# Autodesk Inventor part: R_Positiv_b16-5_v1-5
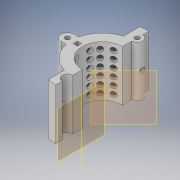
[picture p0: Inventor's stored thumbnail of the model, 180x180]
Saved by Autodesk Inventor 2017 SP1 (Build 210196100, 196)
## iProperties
Part Number: R_Positiv_b16-5_v1-5
Material: Generisch
Document SubType Name: Modeling
Designer: haesner
Density: 1 g/cm^3
Appearance: Vorgabe
Part Number: R_Positiv_b16-5_v1-5_3D-Druck
Author: haesner
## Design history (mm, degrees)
sketch "Skizze1"
  geometry: L1 (-26.9, 0)-(7.4, 0) reference; L2 (0, 22)-(0, 19); L3 (0, 9.5)-(0, 14); L4 (0, -22)-(0, -19); L5 (0, -9.5)-(0, -14); L6 (0, -30.8)-(0, 30.8) reference; C1 r 1.15 at (-16.5, 0); C2 r 1.15 at (0, 16.5); A1 r 22 centre (0, 0) between (0, 22) and (0, -22); A2 r 9.5 centre (0, 0) between (0, 9.5) and (0, -9.5); A3 r 2.5 centre (0, 16.5) between (0, 14) and (0, 19); A4 r 2.5 centre (0, -16.5) between (0, -14) and (0, -19); 1 further point
  constraints: 8 end point, 8 point on circle, 6 centre point, 4 collinear, 3 coincident, 3 point on line, 3 vertical, 1 equal radius
  dimensions: "d1" = 22 radius of A1; "d2" = 9.5 radius of A2; "d5" = 2.3 diameter of C1 (= d8); "d7" = 16.5 distance from line of L1 A3.centre (= d12); "d8" = 2.3 diameter of C2; "d10" = 16.5 distance from line of L6 C1.centre (= d12); "d11" = 2.5 radius of A4; "d12" = 16.5 distance from line of L1 A4.centre
extrude "Extrusion2" new body sketch "Skizze1" distance "d13" = 3; taper "d14" = 0 deg
sketch "Skizze5"
  geometry: L1 (-4, -21.633)-(-4, -13.937); L2 (-4, 21.633)-(-4, 13.937); L3 (0, 19)-(0, 22) reference; L4 (0, 9.5)-(0, 14) reference; L5 (0, -22)-(0, -19) reference; L6 (0, -14)-(0, -9.5) reference; L7 (-26.9, 0)-(7.4, 0) reference; L8 (-16.5, -3)-(-14.186, -3); L9 (-16.5, 3)-(-14.186, 3); C1 r 1.15 at (0, 16.5) reference; C2 r 1.15 at (-16.5, 0) reference; A1 r 14.5 centre (0, 0) between (-4, 13.937) and (-4, -13.937); A2 r 9.5 centre (0, 0) between (0, 9.5) and (0, -9.5) reference; A3 r 22 centre (0, 0) between (0, 22) and (-4, 21.633); A4 r 22 centre (0, 0) between (-4, -21.633) and (0, -22); A5 r 2.5 centre (0, 16.5) between (0, 14) and (0, 19) reference; A6 r 2.5 centre (0, -16.5) between (0, -14) and (0, -19) reference; A7 r 3 centre (-16.5, 0) between (-16.5, 3) and (-16.5, -3)
  constraints: 10 point on circle, 8 end point, 4 centre point, 4 coincident, 2 horizontal, 2 vertical, 1 concentric, 1 other
  dimensions: "d22" = 14.5 radius of A1; "d100" = 4 distance between parallel lines of L3 L2; "d101" = 4 distance between parallel lines of L5 L1 (= d100); "d119" = 3 radius of A7; "d120" = 6 distance between parallel lines of L9 L8
extrude "Extrusion5" join sketch "Skizze5" distance "d27" = 18; taper "d28" = 0 deg
workplane "Arbeitsebene4"
sketch "Skizze10"
  geometry: L1 (0, 19)-(0, 22); L2 (0, 9.5)-(0, 14); L3 (0, -14)-(0, -9.5); L4 (0, -22)-(0, -19); C1 r 1.15 at (0, 16.5); C2 r 1.15 at (-16.5, 0) reference; A1 r 22 centre (0, 0) between (0, 22) and (0, -22); A2 r 2.5 centre (0, 16.5) between (0, 14) and (0, 19); A3 r 9.5 centre (0, 0) between (0, 9.5) and (0, -9.5); A4 r 2.5 centre (0, -16.5) between (0, -14) and (0, -19)
  constraints: 8 end point, 8 point on circle, 5 centre point
extrude "Extrusion9" join sketch "Skizze10" distance "d69" = 3; taper "d70" = 0 deg
sketch "Skizze6"
  geometry: L1 (14.4, 7.821)-(14.4, 3.321); L2 (14.4, 3.321)-(10.8, 3.321); L3 (10.8, 3.321)-(10.8, 7.821); L4 (10.8, 7.821)-(7.2, 7.821); L5 (7.2, 7.821)-(7.2, 3.321); L6 (7.2, 3.321)-(3.6, 3.321); L7 (3.6, 3.321)-(3.6, 7.821); L8 (3.6, 7.821)-(0, 7.821); L9 (0, 7.821)-(0, 3.321); L10 (22.585, 5.571)-(-0.758, 5.571); L11 (14.4, 7.821)-(18, 7.821); L12 (18, 7.821)-(18, 3.321); L13 (-8.117, 7.071)-(27.702, 7.071) reference; L14 (-3, 47.871)-(-3, -19.94) reference; 1 further point
  constraints: 24 end point, 7 perpendicular, 6 equal length, 5 point on line, 2 horizontal, 1 vertical, 1 other
  dimensions: "d31" = 3.6 distance of L1.end L2.end; "d32" = 4.5 distance of L1.start L1.end; "d114" = 3 distance between parallel lines of L9 L14; "d115" = 0.75 distance between parallel lines of L13 L11
hole "Bohrung1" sketch "Skizze6" at (14.4, 3.321), (14.4, 7.821), (10.8, 7.821), (10.8, 3.321), (7.2, 3.321), (7.2, 7.821), (3.6, 7.821), (0, 7.821), (0, 3.321), (3.6, 3.321), (18, 7.821), (18, 3.321) diameter "d34" = 2.5; stored, may be unused: countersink angle "d38" = 90 deg, drill point angle "d40" = 118 deg; dims "d35" = 6, "d36" = 4, "d37" = 2, "d39" = 4
workplane "Arbeitsebene5"
sketch "Skizze7"
  geometry: L1 (14.4, -7.821)-(14.4, -3.321); L2 (14.4, -3.321)-(10.8, -3.321); L3 (10.8, -3.321)-(10.8, -7.821); L4 (10.8, -7.821)-(7.2, -7.821); L5 (7.2, -7.821)-(7.2, -3.321); L6 (7.2, -3.321)-(3.6, -3.321); L7 (3.6, -3.321)-(3.6, -7.821); L8 (3.6, -7.821)-(0, -7.821); L9 (0, -7.821)-(0, -3.321); L10 (24.128, -5.571)-(-5.905, -5.571); L11 (-11.912, -7.071)-(30.135, -7.071) reference; L12 (-3, 19.94)-(-3, -47.871) reference; L13 (14.4, -7.821)-(18, -7.821); L14 (18, 0.243)-(18, -20.071) reference; L15 (18, -7.821)-(18, -3.321); 2 further points
  constraints: 24 end point, 8 perpendicular, 6 equal length, 5 point on line, 1 horizontal, 1 vertical, 1 other
  dimensions: "d41" = 4.5 distance of L1.start L1.end; "d42" = 3.6 distance of L1.end L2.end; "d116" = 3 distance between parallel lines of L12 L9; "d117" = 0.75 distance between parallel lines of L11 L13
hole "Bohrung2" sketch "Skizze7" at (14.4, -7.821), (14.4, -3.321), (10.8, -3.321), (10.8, -7.821), (7.2, -7.821), (7.2, -3.321), (3.6, -3.321), (3.6, -7.821), (0, -7.821), (0, -3.321), (18, -3.321), (18, -7.821) diameter "d44" = 2.5; stored, may be unused: countersink angle "d48" = 90 deg, drill point angle "d50" = 118 deg; dims "d45" = 6, "d46" = 4, "d47" = 2, "d49" = 4
workplane "Arbeitsebene6"
sketch "Skizze8"
  geometry: L1 (-14.4, 7)-(-14.4, 13); L2 (-14.4, 13)-(-10.8, 13); L3 (-10.8, 13)-(-10.8, 7); L4 (-10.8, 7)-(-7.2, 7); L5 (-7.2, 7)-(-7.2, 13); L6 (-7.2, 13)-(-3.6, 13); L7 (-3.6, 13)-(-3.6, 7); L8 (-3.6, 7)-(0, 7); L9 (0, 7)-(0, 13); L10 (3, -20.8)-(3, 40.8) reference; L11 (7.8, 10)-(-25.8, 10) reference; L12 (-14.4, 7)-(-18, 7); L13 (-18, 7)-(-18, 13)
  constraints: 22 end point, 7 equal length, 7 perpendicular, 4 point on line, 1 horizontal, 1 symmetric about line, 1 vertical
  dimensions: "d51" = 6 distance of L1.start L1.end; "d52" = 3.6 distance of L1.end L2.end; "d118" = 3 distance between parallel lines of L10 L9
hole "Bohrung3" sketch "Skizze8" at (-14.4, 13), (-14.4, 7), (-10.8, 7), (-10.8, 13), (-7.2, 13), (-7.2, 7), (-3.6, 7), (-3.6, 13), (0, 13), (0, 7), (-18, 7), (-18, 13) diameter "d54" = 2.5; stored, may be unused: countersink angle "d58" = 90 deg, drill point angle "d60" = 0 deg; dims "d55" = 6, "d56" = 4, "d57" = 2, "d59" = 10.8
sketch "Skizze9"
  geometry: L1 (10.817, -2)-(12.845, -2); L2 (10.817, 2)-(12.845, 2); L3 (26.9, 0)-(-7.4, 0) reference; L4 (0, -14)-(0, -9.5) reference; A1 r 9.5 centre (0, 0) between (0, -9.5) and (0, 9.5) reference; A2 r 1.023 centre (2.5, -11.735) between (2.5, -10.712) and (2.5, -12.757); A3 r 11 centre (0, 0) between (2.5, -10.712) and (10.817, -2); A4 r 13 centre (0, 0) between (2.5, -12.757) and (12.845, -2); A5 r 11 centre (0, 0) between (10.817, 2) and (2.5, 10.712); A6 r 13 centre (0, 0) between (12.845, 2) and (2.5, 12.757); A7 r 1.023 centre (2.5, 11.735) between (2.5, 12.757) and (2.5, 10.712); 2 further points
  constraints: 12 point on circle, 6 centre point, 6 vertical alignment, 4 coincident, 4 end point, 2 horizontal, 1 parallel, 1 other
  dimensions: "d121" = 4 distance between parallel lines of L2 L1; "d122" = 11 radius of A5; "d123" = 13 radius of A6; "d124" = 2.5 distance from line of L4 A2.centre
extrude "Extrusion6" cut sketch "Skizze9" distance "d63" = 23; taper "d64" = 0 deg
sketch "Skizze18"
  geometry: L1 (4, -21.633)-(4, -13.937) reference; L2 (4, 13.937)-(4, 21.633) reference; L3 (26.9, 0)-(-7.4, 0) reference; L4 (16.5, 3)-(14.186, 3) reference; L5 (14.186, -3)-(16.5, -3) reference; A1 r 14.5 centre (0, 0) between (4, -13.937) and (4, 13.937) reference; A2 r 14.5 centre (0, 0) between (14.186, 3) and (4, 13.937); A3 r 14.5 centre (0, 0) between (4, -13.937) and (14.186, -3); A4 r 3 centre (16.5, 0) between (16.5, -3) and (16.5, 3) reference; A5 r 22 centre (0, 0) between (0, -22) and (0, 22) reference; 2 further points
  constraints: 4 point on circle, 2 centre point, 1 coincident, 1 concentric
extrude "Extrusion16" cut sketch "Skizze18" distance "d103" = 30; taper "d104" = 0 deg
sketch "Skizze20"
  geometry: L1 (10.817, -1.014)-(12.845, -1.014); L2 (12.845, -1.014)-(12.845, 1.014); L3 (12.845, 1.014)-(10.817, 1.014); L4 (10.817, 1.014)-(10.817, -1.014); L5 (23.9, 0)-(-6.9, 0) reference; L6 (10.817, -2)-(12.845, -2) reference; 1 further point
  constraints: 8 end point, 3 perpendicular, 2 parallel, 1 horizontal, 1 point on line, 1 other
extrude "Extrusion17" cut sketch "Skizze20" distance "d125" = 40; taper "d126" = 0 deg
sketch "Skizze21"
  geometry: L1 (10.817, -2)-(12.845, -2) reference; L2 (12.845, -1.014)-(10.817, -1.014) reference; L3 (10.817, 1.014)-(12.845, 1.014) reference; L4 (12.845, 2)-(10.817, 2) reference; L5 (10.817, -2)-(10.817, -1.014); L6 (10.817, 2)-(10.817, 1.014); L7 (12.845, 1.014)-(12.845, 2); L8 (10.817, -1.014)-(12.845, -1.014) reference; L9 (12.845, -1.014)-(12.845, -2); A1 r 11 centre (0, 0) between (2.5, -10.712) and (10.817, -2) reference; 1 further point
  constraints: 8 end point, 2 vertical, 1 parallel, 1 perpendicular
extrude "Extrusion18" cut sketch "Skizze21" distance "d127" = 10; taper "d128" = 0 deg
sketch "Skizze19"
  geometry: L1 (0, -9.167)-(0, 52.433) reference; L2 (-4.8, 21.633)-(28.8, 21.633) reference; L3 (12, 38.133)-(12, 5.133); 1 further point
  constraints: 2 end point, 1 symmetric about line, 1 vertical
  dimensions: "d105" = 33 distance of L3.start L3.end; "d106" = 12 distance between parallel lines of L1 L3
hole "Bohrung4" sketch "Skizze19" at (12, 38.133), (12, 5.133) diameter "d107" = 2.3; stored, may be unused: countersink angle "d111" = 90 deg, drill point angle "d113" = 118 deg; dims "d108" = 6, "d109" = 4, "d110" = 2, "d112" = 8
sketch "Skizze12"
  geometry: L1 (5, 18.848)-(5, 16.248); L2 (16.248, -5)-(18.848, -5); L3 (16.248, 5)-(18.848, 5); L4 (5, -16.248)-(5, -18.848); L5 (0, -30.8)-(0, 30.8) reference; L6 (26.9, 0)-(-7.4, 0) reference; A1 r 19.5 centre (0, 0) between (18.848, 5) and (5, 18.848); A2 r 19.5 centre (0, 0) between (5, -18.848) and (18.848, -5); A3 r 17 centre (0, 0) between (16.248, 5) and (5, 16.248); A4 r 17 centre (0, 0) between (5, -16.248) and (16.248, -5); A5 r 1.3 centre (17.548, 5) between (16.248, 5) and (18.848, 5); A6 r 1.3 centre (17.548, -5) between (18.848, -5) and (16.248, -5); A7 r 1.3 centre (5, 17.548) between (5, 18.848) and (5, 16.248); A8 r 1.3 centre (5, -17.548) between (5, -16.248) and (5, -18.848); 3 further points
  constraints: 20 point on circle, 8 centre point, 8 end point, 6 coincident, 4 midpoint, 2 vertical, 1 concentric, 1 horizontal, 1 perpendicular, 1 symmetric about line, 1 other
  dimensions: "d80" = 19.5 radius of A1; "d81" = 17 radius of A3; "d82" = 10 distance between parallel lines of L2 L3; "d83" = 5 distance between parallel lines of L5 L1
extrude "Extrusion11" cut sketch "Skizze12" distance "d84" = 30; taper "d85" = 0 deg
node "Volumenkörper2"
